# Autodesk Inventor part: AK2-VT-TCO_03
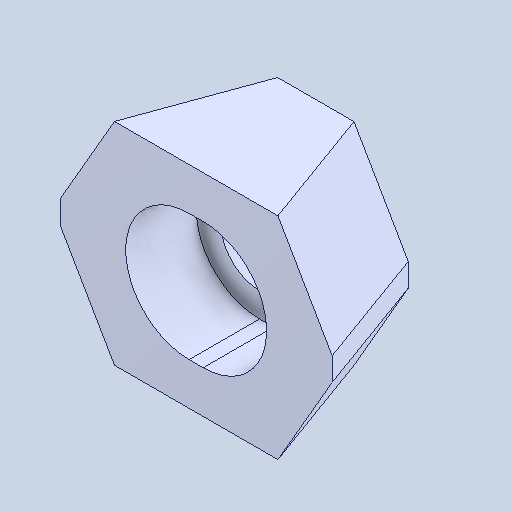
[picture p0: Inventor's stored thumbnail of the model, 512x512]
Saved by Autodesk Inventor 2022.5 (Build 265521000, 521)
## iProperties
Created: 2024-07
Part Number: AK2-VT-TCO_03
Material: 一般
Document SubType Name: Modeling
Designer: ImaoCorp
Density: 1 g/cm^3
Appearance: 既定
Author: ImaoCorp
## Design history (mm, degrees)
feature "AK2-VT-TCO_03"
node "ソリッド1"
